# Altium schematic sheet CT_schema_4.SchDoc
size 289 x 230 mm
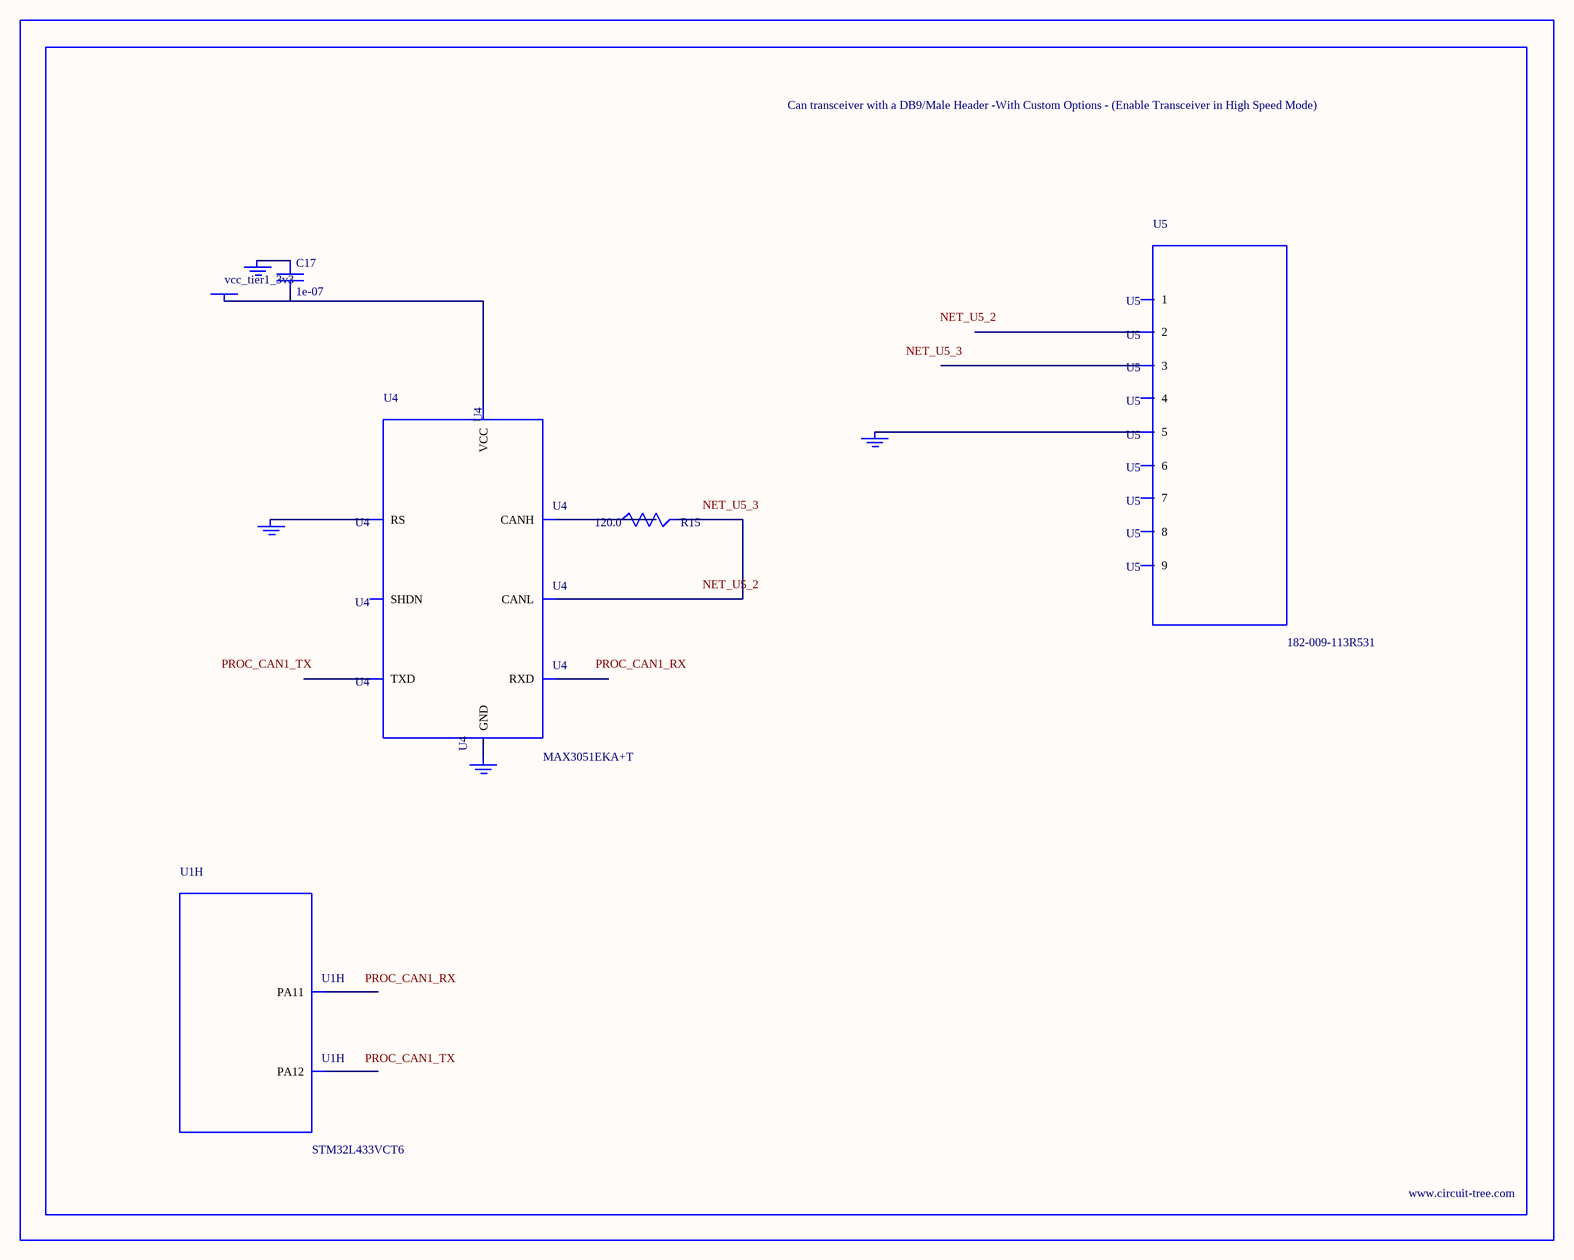
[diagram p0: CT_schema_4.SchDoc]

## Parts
BORDER3  (no value)
C17  1e-07  [C0402]
GND_INSTANCE_3_0  (no value)
GND_INSTANCE_3_1  (no value)
GND_INSTANCE_3_2  (no value)
GND_INSTANCE_3_3  (no value)
POWER_INSTANCE_3_0  vcc_tier1_3v3
R15  120.0  [R0603]
U1  STM32L433VCT6  [LQFP100]  (part H of 9)
U4  MAX3051EKA+T  [SOT-23-8]
U5  182-009-113R531  [182-009-MALE]

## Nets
NetC17_1: C17.1 GND_INSTANCE_3_0.0(GND)
NetC17_2: C17.2 POWER_INSTANCE_3_0.0(PWR) U4.3(VCC)
NetGND_INSTANCE_3_1_0: GND_INSTANCE_3_1.0(GND) U4.8(RS)
NetGND_INSTANCE_3_2_0: GND_INSTANCE_3_2.0(GND) U4.2(GND)
NetGND_INSTANCE_3_3_0: GND_INSTANCE_3_3.0(GND) U5.5
NetR15_1: R15.1 U4.7(CANH)
NetR15_2: R15.2 U4.6(CANL)

Not connected (* = marked no-connect by the designer): U1 70(PA11) 71(PA12); U4 1(TXD) 4(RXD) 5(SHDN); U5 1 2 3 4 6 7 8 9

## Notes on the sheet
- Labels drawn without touching a wire or pin: NET_U5_2, NET_U5_3, PROC_CAN1_RX, PROC_CAN1_TX

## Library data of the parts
BORDER3 = BORDER_PAGE3
C17 = C0402C104K3RACTU
GND_INSTANCE_3_0-GND_INSTANCE_3_3 = GND
POWER_INSTANCE_3_0 = PWR
R15 = RC0603JR-07120RL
